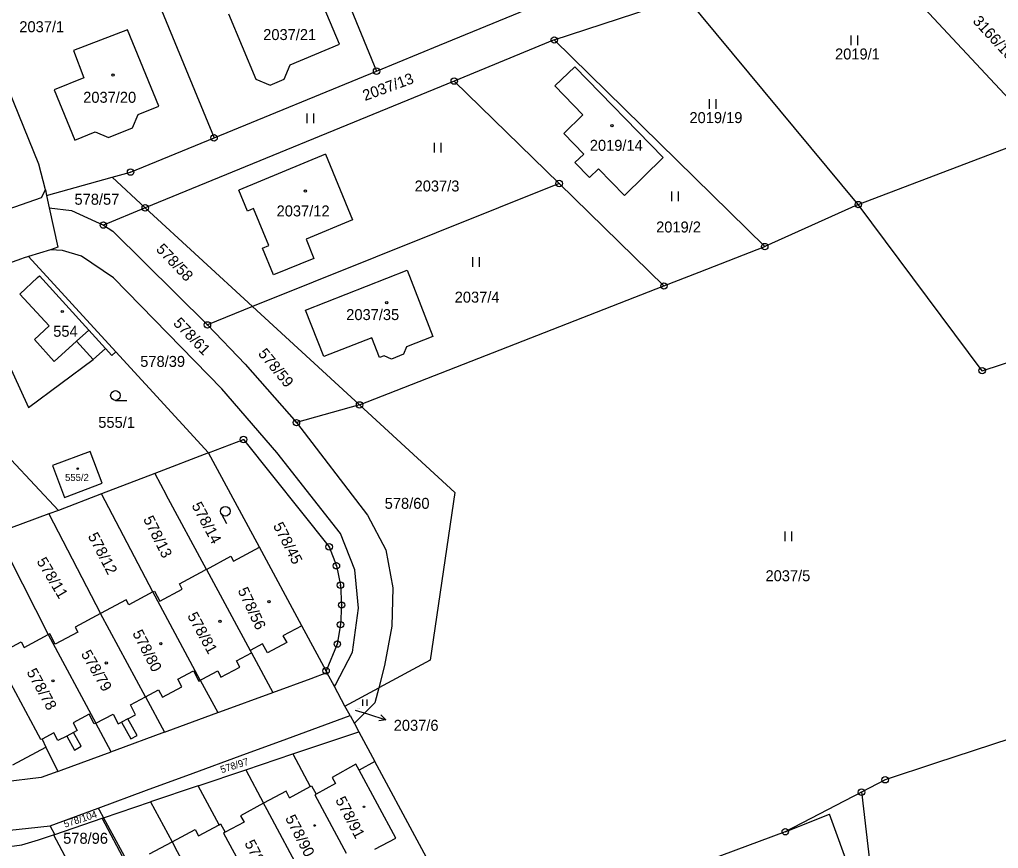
# Model space of a CAD drawing. Extents: x -736345 to -729997, y -1130177 to -1122501.
# Drawn here: x -732915.2 to -732763.4, y -1127440.7 to -1127312.1 of the extents above; entities that cross this region are included whole.
import ezdxf

# ---------------------------------------------------------------- set-up
doc = ezdxf.new("R2010")
doc.units = 0
for name, color, linetype in [('Vrstva 1', 7, 'Continuous'), ('Vrstva 16', 7, 'Continuous'), ('Vrstva 18', 7, 'Continuous'), ('Vrstva 19', 7, 'Continuous'), ('Vrstva 25', 7, 'Continuous'), ('Vrstva 4', 7, 'Continuous')]:
    doc.layers.add(name, color=color, linetype=linetype)

msp = doc.modelspace()

# ---------------------------------------------------------------- linework, layer by layer
at = {"layer": 'Vrstva 1'}
for points in [[(-732871.63, -1127291.34), (-732859.83, -1127320.07)], [(-732897.23, -1127300.77), (-732885.05, -1127330.42)], [(-732865.58, -1127315.91), (-732869.5, -1127306.54)], [(-732785.09, -1127340.77), (-732811.96, -1127308.4)], [(-732756.54, -1127329.92), (-732776.31, -1127308.71)], [(-732912.21, -1127334.51), (-732922.29, -1127309.89)], [(-732850.06, -1127316.06), (-732834.54, -1127309.69)], [(-732832.26, -1127315.24), (-732814.67, -1127309.5)], [(-732882.82, -1127311.18), (-732878.59, -1127321.32)], [(-732898.45, -1127313.65), (-732906.86, -1127316.88)], [(-732893.6, -1127325.52), (-732898.45, -1127313.65)], [(-732832.26, -1127315.24), (-732847.78, -1127321.61)], [(-732799.61, -1127347.29), (-732832.26, -1127315.24)], [(-732906.86, -1127316.88), (-732905.23, -1127321.12)], [(-732873.25, -1127319.1), (-732865.58, -1127315.91)], [(-732859.83, -1127320.07), (-732850.06, -1127316.06)], [(-732874.17, -1127321.33), (-732873.25, -1127319.1)], [(-732829.06, -1127319.42), (-732832.2, -1127322.34)], [(-732815.36, -1127333.49), (-732829.06, -1127319.42)], [(-732905.23, -1127321.12), (-732909.83, -1127322.96)], [(-732885.05, -1127330.42), (-732859.83, -1127320.07)], [(-732878.59, -1127321.32), (-732876.36, -1127322.27)], [(-732876.36, -1127322.27), (-732874.17, -1127321.33)], [(-732909.83, -1127322.96), (-732906.66, -1127330.76)], [(-732847.78, -1127321.61), (-732895.72, -1127341.28)], [(-732831.51, -1127337.5), (-732847.78, -1127321.61)], [(-732832.2, -1127322.34), (-732827.81, -1127326.83)], [(-732896.8, -1127326.81), (-732893.6, -1127325.52)], [(-732897.69, -1127328.87), (-732896.8, -1127326.81)], [(-732827.81, -1127326.83), (-732830.79, -1127329.75)], [(-732901.4, -1127330.35), (-732897.69, -1127328.87)], [(-732906.66, -1127330.76), (-732903.49, -1127329.49)], [(-732903.49, -1127329.49), (-732901.4, -1127330.35)], [(-732898, -1127335.73), (-732885.05, -1127330.42)], [(-732830.79, -1127329.75), (-732827.7, -1127332.95)], [(-732785.09, -1127340.77), (-732756.54, -1127329.92)], [(-732867.74, -1127332.97), (-732881.22, -1127338.52)], [(-732867.74, -1127332.97), (-732863.55, -1127343.14)], [(-732827.7, -1127332.95), (-732829.09, -1127334.25)], [(-732821.36, -1127339.35), (-732815.36, -1127333.49)], [(-732911.22, -1127338.5), (-732912.21, -1127334.51)], [(-732829.09, -1127334.25), (-732826.8, -1127336.59)], [(-732911.03, -1127339.37), (-732900.88, -1127336.53)], [(-732900.88, -1127336.53), (-732898, -1127335.73)], [(-732900.88, -1127336.53), (-732895.72, -1127341.28)], [(-732826.8, -1127336.59), (-732825.42, -1127335.21)], [(-732825.42, -1127335.21), (-732821.36, -1127339.35)], [(-732831.51, -1127337.5), (-732879.1, -1127356.57)], [(-732815.24, -1127353.4), (-732831.51, -1127337.5)], [(-732939.08, -1127349.18), (-732911.82, -1127339.65)], [(-732911.82, -1127339.65), (-732911.22, -1127338.5)], [(-732911.22, -1127338.5), (-732911.03, -1127339.37)], [(-732911.03, -1127339.37), (-732910.61, -1127341.26)], [(-732879.88, -1127341.79), (-732881.22, -1127338.52)], [(-732910.61, -1127341.26), (-732907.17, -1127341.69)], [(-732910.61, -1127341.26), (-732909.26, -1127347.36)], [(-732785.09, -1127340.77), (-732799.61, -1127347.29)], [(-732765.88, -1127366.54), (-732785.09, -1127340.77)], [(-732907.17, -1127341.69), (-732902.22, -1127343.95)], [(-732895.72, -1127341.28), (-732902.22, -1127343.95)], [(-732895.72, -1127341.28), (-732879.1, -1127356.57)], [(-732878.93, -1127341.4), (-732879.88, -1127341.79)], [(-732876.57, -1127347.12), (-732878.93, -1127341.4)], [(-732902.22, -1127343.95), (-732900.74, -1127344.92)], [(-732863.55, -1127343.14), (-732870.78, -1127346.16)], [(-732900.74, -1127344.92), (-732886.08, -1127359.44)], [(-732877.52, -1127347.51), (-732876.57, -1127347.12)], [(-732870.78, -1127346.16), (-732869.56, -1127349.14)], [(-732809.76, -1127351.26), (-732799.61, -1127347.29)], [(-732913.86, -1127348.82), (-732914.65, -1127349.1)], [(-732910.43, -1127347.79), (-732913.86, -1127348.82)], [(-732900.29, -1127363.61), (-732913.86, -1127348.82)], [(-732909.26, -1127347.36), (-732910.43, -1127347.79)], [(-732908.54, -1127347.88), (-732910.43, -1127347.79)], [(-732905.63, -1127348.8), (-732908.54, -1127347.88)], [(-732900.66, -1127352.13), (-732905.63, -1127348.8)], [(-732875.8, -1127351.69), (-732877.52, -1127347.51)], [(-732914.93, -1127349.2), (-732923.1, -1127352.09)], [(-732914.65, -1127349.1), (-732914.93, -1127349.2)], [(-732869.56, -1127349.14), (-732875.8, -1127351.69)], [(-732870.84, -1127357.14), (-732855.1, -1127350.97), (-732851.08, -1127361.22), (-732855.18, -1127362.85), (-732855.65, -1127364), (-732857.52, -1127364.74), (-732858.67, -1127364.23), (-732859.37, -1127364.49), (-732860.58, -1127361.42), (-732868.02, -1127364.34), (-732870.84, -1127357.14)], [(-732815.24, -1127353.4), (-732809.76, -1127351.26)], [(-732923.1, -1127352.09), (-732913.85, -1127372.23)], [(-732883.85, -1127369.37), (-732900.66, -1127352.13)], [(-732862.47, -1127371.85), (-732815.24, -1127353.4)], [(-732879.1, -1127356.57), (-732886.08, -1127359.44)], [(-732879.1, -1127356.57), (-732862.47, -1127371.85)], [(-732765.88, -1127366.54), (-732737.77, -1127357.37)], [(-732886.08, -1127359.44), (-732880.22, -1127365.51)], [(-732903.79, -1127364.82), (-732901.9, -1127363.12)], [(-732901.9, -1127363.12), (-732900.93, -1127364.19)], [(-732900.93, -1127364.19), (-732900.29, -1127363.61)], [(-732900.29, -1127363.61), (-732885.9, -1127379.3)], [(-732913.85, -1127372.23), (-732903.79, -1127364.82)], [(-732880.22, -1127365.51), (-732872.27, -1127374.6)], [(-732875.33, -1127379.22), (-732883.85, -1127369.37)], [(-732923.9, -1127372.5), (-732909.17, -1127388.22)], [(-732862.47, -1127371.85), (-732872.27, -1127374.6)], [(-732862.47, -1127371.85), (-732847.71, -1127385.43)], [(-732872.27, -1127374.6), (-732861.24, -1127388.95)], [(-732885.9, -1127379.3), (-732880.48, -1127377.22)], [(-732880.48, -1127377.22), (-732867.18, -1127393.87)], [(-732904.29, -1127379.06), (-732910.12, -1127381.23)], [(-732902.43, -1127383.99), (-732904.29, -1127379.06)], [(-732865.43, -1127391.81), (-732875.33, -1127379.22)], [(-732885.9, -1127379.3), (-732894.24, -1127382.5)], [(-732885.19, -1127380.62), (-732885.9, -1127379.3)], [(-732878.01, -1127393.93), (-732885.19, -1127380.62)], [(-732910.12, -1127381.23), (-732908.27, -1127386.21)], [(-732894.24, -1127382.5), (-732902.5, -1127385.66)], [(-732894.24, -1127382.5), (-732892.47, -1127385.79)], [(-732908.27, -1127386.21), (-732902.43, -1127383.99)], [(-732902.5, -1127385.66), (-732909.17, -1127388.22)], [(-732894.53, -1127400.87), (-732902.5, -1127385.66)], [(-732886.23, -1127397.36), (-732892.47, -1127385.79)], [(-732847.71, -1127385.43), (-732851.53, -1127411.44)], [(-732909.17, -1127388.22), (-732910.67, -1127388.77)], [(-732910.67, -1127388.77), (-732918.8, -1127391.73)], [(-732910.67, -1127388.77), (-732902.65, -1127404.19)], [(-732861.24, -1127388.95), (-732858.41, -1127394.35)], [(-732918.8, -1127391.73), (-732910.76, -1127407.47)], [(-732863.23, -1127397.41), (-732865.43, -1127391.81)], [(-732882.03, -1127396.1), (-732878.01, -1127393.93)], [(-732871.45, -1127406.11), (-732878.01, -1127393.93)], [(-732867.18, -1127393.87), (-732866.07, -1127396.8)], [(-732858.41, -1127394.35), (-732857.3, -1127400.23)], [(-732886.23, -1127397.36), (-732882.46, -1127395.29)], [(-732882.46, -1127395.29), (-732882.03, -1127396.1)], [(-732886.23, -1127397.36), (-732886.48, -1127397.5)], [(-732886.23, -1127397.36), (-732879.42, -1127409.96)], [(-732866.07, -1127396.8), (-732865.44, -1127399.82)], [(-732862.65, -1127403.38), (-732863.23, -1127397.41)], [(-732890.41, -1127399.63), (-732886.48, -1127397.5)], [(-732893.47, -1127402.32), (-732889.98, -1127400.43)], [(-732889.98, -1127400.43), (-732890.41, -1127399.63)], [(-732865.44, -1127399.82), (-732865.25, -1127402.89)], [(-732857.3, -1127400.23), (-732857.48, -1127406.16)], [(-732894.53, -1127400.87), (-732898.28, -1127402.87)], [(-732894.53, -1127400.87), (-732894.3, -1127400.75)], [(-732887.18, -1127414.56), (-732894.53, -1127400.87)], [(-732894.3, -1127400.75), (-732893.47, -1127402.32)], [(-732898.7, -1127402.09), (-732902.65, -1127404.19)], [(-732898.28, -1127402.87), (-732898.7, -1127402.09)], [(-732865.25, -1127402.89), (-732865.43, -1127405.94)], [(-732863.55, -1127410.23), (-732862.65, -1127403.38)], [(-732902.65, -1127404.19), (-732906.61, -1127406.31)], [(-732895.66, -1127417.15), (-732902.65, -1127404.19)], [(-732906.61, -1127406.31), (-732906.2, -1127407.09)], [(-732867.67, -1127413.11), (-732871.45, -1127406.11)], [(-732865.43, -1127405.94), (-732865.92, -1127408.95)], [(-732857.48, -1127406.16), (-732858.62, -1127412.26)], [(-732914.51, -1127409.46), (-732910.76, -1127407.47)], [(-732910.54, -1127407.36), (-732910.76, -1127407.47)], [(-732910.76, -1127407.47), (-732903.4, -1127421.22)], [(-732909.69, -1127408.95), (-732910.54, -1127407.36)], [(-732906.2, -1127407.09), (-732909.69, -1127408.95)], [(-732918.93, -1127410.73), (-732914.95, -1127408.62)], [(-732914.95, -1127408.62), (-732914.51, -1127409.46)], [(-732865.92, -1127408.95), (-732867.67, -1127413.11)], [(-732911.93, -1127423.77), (-732918.93, -1127410.73)], [(-732879.42, -1127409.96), (-732879.25, -1127410.3)], [(-732879.25, -1127410.3), (-732875.93, -1127416.45)], [(-732866.21, -1127415.27), (-732863.55, -1127410.23)], [(-732851.53, -1127411.44), (-732859.5, -1127415.74)], [(-732858.62, -1127412.26), (-732859.5, -1127415.74)], [(-732869.98, -1127414.27), (-732867.53, -1127413.37)], [(-732867.67, -1127413.11), (-732867.53, -1127413.37)], [(-732866.36, -1127415.55), (-732867.53, -1127413.37)], [(-732887.18, -1127414.56), (-732884.48, -1127419.59)], [(-732875.93, -1127416.45), (-732869.98, -1127414.27)], [(-732866.36, -1127415.55), (-732866.21, -1127415.27)], [(-732864.74, -1127418.56), (-732866.36, -1127415.55)], [(-732895.66, -1127417.15), (-732892.71, -1127422.62)], [(-732884.14, -1127419.47), (-732875.93, -1127416.45)], [(-732864.74, -1127418.56), (-732859.5, -1127415.74)], [(-732859.5, -1127415.74), (-732860.09, -1127418.07)], [(-732863.94, -1127420.04), (-732864.74, -1127418.56)], [(-732860.09, -1127418.07), (-732863.13, -1127421.14)], [(-732892.34, -1127422.48), (-732884.48, -1127419.59)], [(-732884.48, -1127419.59), (-732884.14, -1127419.47)], [(-732873.77, -1127423.65), (-732863.94, -1127420.04)], [(-732863.94, -1127420.04), (-732863.27, -1127421.28)], [(-732901.03, -1127425.66), (-732903.4, -1127421.22)], [(-732863.27, -1127421.28), (-732863.13, -1127421.14)], [(-732863.27, -1127421.28), (-732862.57, -1127422.58)], [(-732892.71, -1127422.62), (-732900.55, -1127425.49)], [(-732892.71, -1127422.62), (-732892.34, -1127422.48)], [(-732872.83, -1127426), (-732862.57, -1127422.58)], [(-732862.57, -1127422.58), (-732860.08, -1127427.19)], [(-732911.72, -1127423.72), (-732911.93, -1127423.77)], [(-732911.72, -1127423.72), (-732911.13, -1127424.93)], [(-732881.02, -1127426.31), (-732873.77, -1127423.65)], [(-732761.42, -1127423.6), (-732773.12, -1127427.44)], [(-732911.13, -1127424.93), (-732909.29, -1127428.7)], [(-732908.75, -1127428.5), (-732901.03, -1127425.66)], [(-732900.55, -1127425.49), (-732901.03, -1127425.66)], [(-732888.28, -1127428.97), (-732881.02, -1127426.31)], [(-732880.13, -1127428.44), (-732872.83, -1127426)], [(-732872.83, -1127426), (-732870.12, -1127431.05)], [(-732860.08, -1127427.19), (-732862.51, -1127428.53)], [(-732846.94, -1127451.57), (-732860.08, -1127427.19)], [(-732773.12, -1127427.44), (-732780.92, -1127430)], [(-732909.29, -1127428.7), (-732911.86, -1127429.65)], [(-732909.29, -1127428.7), (-732908.75, -1127428.5)], [(-732895.53, -1127431.64), (-732888.28, -1127428.97)], [(-732887.51, -1127430.93), (-732880.13, -1127428.44)], [(-732880.13, -1127428.44), (-732877.35, -1127433.65)], [(-732856.82, -1127439.08), (-732862.51, -1127428.53)], [(-732911.86, -1127429.65), (-732917.83, -1127430.37)], [(-732780.92, -1127430), (-732784.6, -1127431.92)], [(-732903.01, -1127434.39), (-732895.53, -1127431.64)], [(-732887.51, -1127430.93), (-732894.9, -1127433.43)], [(-732884.27, -1127436.97), (-732887.51, -1127430.93)], [(-732870.12, -1127431.05), (-732869.91, -1127430.94)], [(-732869.91, -1127430.94), (-732869.22, -1127432.23)], [(-732869.22, -1127432.23), (-732869.43, -1127432.35)], [(-732869.43, -1127432.35), (-732864.57, -1127441.39)], [(-732784.6, -1127431.92), (-732796.42, -1127438.06)], [(-732784.6, -1127431.92), (-732784.56, -1127432.3)], [(-732784.56, -1127432.3), (-732778.3, -1127486.15)], [(-732902.19, -1127435.9), (-732894.9, -1127433.43)], [(-732894.9, -1127433.43), (-732891.55, -1127439.62)], [(-732876.81, -1127434.65), (-732877.35, -1127433.65)], [(-732910.49, -1127437.13), (-732903.01, -1127434.39)], [(-732903.01, -1127434.39), (-732902.86, -1127434.67)], [(-732902.86, -1127434.67), (-732902.19, -1127435.9)], [(-732871.29, -1127445), (-732876.81, -1127434.65)], [(-732796.42, -1127438.06), (-732789.55, -1127435.35)], [(-732782.65, -1127454.43), (-732789.55, -1127435.35)], [(-732909.76, -1127438.48), (-732902.41, -1127435.98)], [(-732902.41, -1127435.98), (-732902.19, -1127435.9)], [(-732898.72, -1127442.87), (-732902.41, -1127435.98)], [(-732902.19, -1127435.9), (-732897.72, -1127444.2)], [(-732884.27, -1127436.97), (-732884.03, -1127436.85)], [(-732884.03, -1127436.85), (-732883.33, -1127438.15)], [(-732918.7, -1127438.04), (-732910.49, -1127437.13)], [(-732910.43, -1127437.24), (-732910.49, -1127437.13)], [(-732909.76, -1127438.48), (-732910.43, -1127437.24)], [(-732883.33, -1127438.15), (-732883.59, -1127438.29)], [(-732883.59, -1127438.29), (-732878.64, -1127447.46)], [(-732796.42, -1127438.06), (-732827.88, -1127449.76)], [(-732914.89, -1127440.1), (-732912.26, -1127439.34)], [(-732912.26, -1127439.34), (-732909.94, -1127438.54)], [(-732909.94, -1127438.54), (-732909.76, -1127438.48)], [(-732909.94, -1127438.54), (-732906.11, -1127445.71)], [(-732891.55, -1127439.62), (-732891.02, -1127440.6)], [(-732860.12, -1127440.78), (-732856.82, -1127439.08)], [(-732917.57, -1127440.47), (-732914.89, -1127440.1)], [(-732885.36, -1127451.06), (-732891.02, -1127440.6)]]:
    msp.add_lwpolyline(points, dxfattribs=at)
at = {"layer": 'Vrstva 16'}
msp.add_lwpolyline([(-732863.14, -1127419.18), (-732861.23, -1127419.79)], dxfattribs=at)
at = {"layer": 'Vrstva 25'}
for points in [[(-732786.207, -1127316.025), (-732786.207, -1127314.525)], [(-732785.173, -1127316.025), (-732785.173, -1127314.525)], [(-732808.187, -1127325.895), (-732808.187, -1127324.395)], [(-732807.153, -1127325.895), (-732807.153, -1127324.395)], [(-732870.607, -1127328.135), (-732870.607, -1127326.635)], [(-732869.573, -1127328.135), (-732869.573, -1127326.635)], [(-732850.847, -1127332.715), (-732850.847, -1127331.215)], [(-732849.813, -1127332.715), (-732849.813, -1127331.215)], [(-732814.007, -1127340.235), (-732814.007, -1127338.735)], [(-732812.973, -1127340.235), (-732812.973, -1127338.735)], [(-732844.887, -1127350.435), (-732844.887, -1127348.935)], [(-732843.853, -1127350.435), (-732843.853, -1127348.935)], [(-732900.34, -1127371.14), (-732898.59, -1127371.14)], [(-732883.96, -1127388.71), (-732883.101, -1127390.234)], [(-732796.427, -1127392.985), (-732796.427, -1127391.485)], [(-732795.393, -1127392.985), (-732795.393, -1127391.485)], [(-732861.976, -1127418.542), (-732861.976, -1127417.537)], [(-732861.283, -1127418.542), (-732861.283, -1127417.537)], [(-732861.23, -1127419.79), (-732858.374, -1127420.707)], [(-732859.173, -1127419.925), (-732858.374, -1127420.707), (-732859.479, -1127420.877)]]:
    msp.add_lwpolyline(points, dxfattribs=at)
for centre, radius in [((-732832.26, -1127315.24), 0.5), ((-732832.26, -1127315.24), 0.032), ((-732859.83, -1127320.07), 0.5), ((-732900.72, -1127320.68), 0.175), ((-732859.83, -1127320.07), 0.032), ((-732847.78, -1127321.61), 0.5), ((-732847.78, -1127321.61), 0.032), ((-732823.32, -1127328.53), 0.175), ((-732885.05, -1127330.42), 0.5), ((-732885.05, -1127330.42), 0.032), ((-732898, -1127335.73), 0.5), ((-732898, -1127335.73), 0.032), ((-732831.51, -1127337.5), 0.5), ((-732831.51, -1127337.5), 0.032), ((-732870.87, -1127338.68), 0.175), ((-732895.72, -1127341.28), 0.5), ((-732895.72, -1127341.28), 0.032), ((-732785.09, -1127340.77), 0.5), ((-732785.09, -1127340.77), 0.032), ((-732902.22, -1127343.95), 0.499), ((-732902.22, -1127343.95), 0.0318), ((-732799.61, -1127347.29), 0.5), ((-732799.61, -1127347.29), 0.032), ((-732815.24, -1127353.4), 0.5), ((-732815.24, -1127353.4), 0.032), ((-732858.25, -1127356), 0.175), ((-732908.59, -1127357.36), 0.175), ((-732886.08, -1127359.44), 0.5), ((-732886.08, -1127359.44), 0.032), ((-732765.88, -1127366.54), 0.5), ((-732765.88, -1127366.54), 0.032), ((-732900.34, -1127370.39), 0.75), ((-732862.47, -1127371.85), 0.5), ((-732862.47, -1127371.85), 0.032), ((-732872.27, -1127374.6), 0.5), ((-732872.27, -1127374.6), 0.032), ((-732880.48, -1127377.22), 0.5), ((-732880.48, -1127377.22), 0.032), ((-732906.189, -1127381.73), 0.118), ((-732883.307, -1127388.342), 0.75), ((-732867.18, -1127393.87), 0.5), ((-732867.18, -1127393.87), 0.032), ((-732866.07, -1127396.8), 0.5), ((-732866.07, -1127396.8), 0.032), ((-732865.44, -1127399.82), 0.5), ((-732865.44, -1127399.82), 0.032), ((-732876.54, -1127402.37), 0.175), ((-732865.25, -1127402.89), 0.5), ((-732865.25, -1127402.89), 0.032), ((-732884.13, -1127405.41), 0.175), ((-732865.43, -1127405.94), 0.5), ((-732865.43, -1127405.94), 0.032), ((-732893.31, -1127408.87), 0.174), ((-732865.92, -1127408.95), 0.5), ((-732865.92, -1127408.95), 0.032), ((-732901.77, -1127411.87), 0.175), ((-732867.67, -1127413.11), 0.5), ((-732867.67, -1127413.11), 0.032), ((-732910.04, -1127414.65), 0.175), ((-732780.92, -1127430), 0.5), ((-732780.92, -1127430), 0.032), ((-732784.6, -1127431.92), 0.5), ((-732784.6, -1127431.92), 0.032), ((-732861.78, -1127434.2), 0.118), ((-732869.419, -1127437.09), 0.118), ((-732796.42, -1127438.06), 0.5), ((-732796.42, -1127438.06), 0.032)]:
    msp.add_circle(centre, radius, dxfattribs=at)
at = {"layer": 'Vrstva 4'}
for points in [[(-732912.43, -1127352.09), (-732912.14, -1127351.82)], [(-732904.5, -1127360.23), (-732912.14, -1127351.82)], [(-732912.43, -1127352.09), (-732915.19, -1127354.67)], [(-732915.19, -1127354.67), (-732910.63, -1127359.58)], [(-732910.63, -1127359.58), (-732912.93, -1127361.71)], [(-732906.4, -1127361.96), (-732904.5, -1127360.23)], [(-732901.9, -1127363.12), (-732904.5, -1127360.23)], [(-732912.93, -1127361.71), (-732909.83, -1127365.12)], [(-732909.83, -1127365.12), (-732906.4, -1127361.96)], [(-732906.4, -1127361.96), (-732903.79, -1127364.82)], [(-732871.45, -1127406.11), (-732874.35, -1127407.67)], [(-732874.35, -1127407.67), (-732873.77, -1127408.73)], [(-732877.51, -1127408.93), (-732879.42, -1127409.96)], [(-732876.73, -1127410.33), (-732877.51, -1127408.93)], [(-732873.77, -1127408.73), (-732876.73, -1127410.33)], [(-732881.55, -1127411.54), (-732879.25, -1127410.3)], [(-732883.99, -1127414.06), (-732881.06, -1127412.52)], [(-732881.06, -1127412.52), (-732881.55, -1127411.54)], [(-732890.68, -1127414.42), (-732888.24, -1127413.09)], [(-732888.24, -1127413.09), (-732887.39, -1127414.68)], [(-732886.87, -1127414.4), (-732884.47, -1127413.11)], [(-732884.47, -1127413.11), (-732883.99, -1127414.06)], [(-732893.07, -1127417.2), (-732890.06, -1127415.59)], [(-732890.06, -1127415.59), (-732890.68, -1127414.42)], [(-732887.39, -1127414.68), (-732887.18, -1127414.56)], [(-732887.18, -1127414.56), (-732886.87, -1127414.4)], [(-732898.03, -1127418.4), (-732895.66, -1127417.15)], [(-732895.66, -1127417.15), (-732893.68, -1127416.05)], [(-732893.68, -1127416.05), (-732893.07, -1127417.2)], [(-732897.21, -1127419.91), (-732898.03, -1127418.4)], [(-732904.44, -1127419.81), (-732906.93, -1127421.15)], [(-732903.63, -1127421.34), (-732904.44, -1127419.81)], [(-732903.4, -1127421.22), (-732900.71, -1127419.81)], [(-732900.71, -1127419.81), (-732899.9, -1127421.33)], [(-732898.4, -1127420.57), (-732897.21, -1127419.91)], [(-732906.93, -1127421.15), (-732906.26, -1127422.34)], [(-732903.4, -1127421.22), (-732903.63, -1127421.34)], [(-732899.9, -1127421.33), (-732899.39, -1127421.09)], [(-732898.4, -1127420.57), (-732899.39, -1127421.09)], [(-732899.39, -1127421.09), (-732897.95, -1127423.63)], [(-732896.96, -1127423.13), (-732898.4, -1127420.57)], [(-732909.9, -1127422.74), (-732911.72, -1127423.72)], [(-732909.3, -1127423.93), (-732909.9, -1127422.74)], [(-732907.91, -1127423.22), (-732909.3, -1127423.93)], [(-732906.86, -1127422.65), (-732907.91, -1127423.22)], [(-732907.91, -1127423.22), (-732906.72, -1127425.39)], [(-732906.26, -1127422.34), (-732906.86, -1127422.65)], [(-732905.67, -1127424.81), (-732906.86, -1127422.65)], [(-732897.95, -1127423.63), (-732896.96, -1127423.13)], [(-732916.25, -1127427.67), (-732911.13, -1127424.93)], [(-732906.72, -1127425.39), (-732905.67, -1127424.81)], [(-732863.03, -1127427.59), (-732866.74, -1127429.64)], [(-732862.51, -1127428.53), (-732863.03, -1127427.59)], [(-732866.22, -1127430.58), (-732869.22, -1127432.23)], [(-732866.74, -1127429.64), (-732866.22, -1127430.58)], [(-732873.86, -1127431.77), (-732877.35, -1127433.65)], [(-732873.33, -1127432.78), (-732873.86, -1127431.77)], [(-732873.33, -1127432.78), (-732870.12, -1127431.05)], [(-732877.35, -1127433.65), (-732880.92, -1127435.58)], [(-732880.38, -1127436.57), (-732883.33, -1127438.15)], [(-732880.92, -1127435.58), (-732880.38, -1127436.57)], [(-732891.55, -1127439.62), (-732887.99, -1127437.71)], [(-732887.99, -1127437.71), (-732887.47, -1127438.69)], [(-732887.47, -1127438.69), (-732884.27, -1127436.97)], [(-732895.05, -1127441.49), (-732891.55, -1127439.62)]]:
    msp.add_lwpolyline(points, dxfattribs=at)

# ---------------------------------------------------------------- texts
at = {"layer": 'Vrstva 16'}
for s, p in [('2037/6', (-732857.17, -1127422.4)), ('578/96', (-732908.457, -1127439.93))]:
    msp.add_text(s, height=1.7, dxfattribs=at).set_placement(p)
at = {"layer": 'Vrstva 18'}
for s, height, p in [('2037/1', 1.7, (-732915.26, -1127314.03)), ('2019/1', 1.7, (-732788.7, -1127318.26)), ('2019/19', 1.7, (-732811.29, -1127328.13)), ('2037/3', 1.7, (-732853.93, -1127338.74)), ('578/57', 1.7, (-732906.7, -1127340.8)), ('2019/2', 1.7, (-732816.46, -1127345.1)), ('2037/4', 1.7, (-732847.71, -1127355.98)), ('578/39', 1.7, (-732896.5, -1127365.95)), ('555/1', 1.7, (-732903.01, -1127375.41)), ('578/60', 1.7, (-732858.57, -1127387.97)), ('2037/5', 1.7, (-732799.49, -1127399.2)), ('2037/6', 0.1, (-732862.94, -1127418.98))]:
    msp.add_text(s, height=height, dxfattribs=at).set_placement(p)
for s, height, rotation, p in [('3166/16', 1.7, 312.60249, (-732767.438, -1127312.401)), ('2037/13', 1.7, 20.20016, (-732861.622, -1127324.714)), ('578/58', 1.7, 313.70249, (-732894.158, -1127347.806)), ('578/61', 1.7, 313.80249, (-732891.488, -1127359.275)), ('578/59', 1.7, 309.50246, (-732878.299, -1127363.937)), ('578/14', 1.7, 298.00237, (-732888.58, -1127387.452)), ('578/13', 1.7, 296.50236, (-732896.082, -1127389.559)), ('578/45', 1.7, 297.30236, (-732875.941, -1127390.575)), ('578/12', 1.7, 297.30236, (-732904.671, -1127392.175)), ('578/11', 1.7, 300.90239, (-732912.636, -1127396.118)), ('578/97', 1.1, 17.60014, (-732883.87, -1127428.999)), ('578/104', 1.1, 18.00014, (-732908.162, -1127437.448))]:
    msp.add_text(s, height=height, rotation=rotation, dxfattribs=at).set_placement(p)
at = {"layer": 'Vrstva 19'}
for s, height, p in [('2037/21', 1.7, (-732877.42, -1127315.25)), ('2037/20', 1.7, (-732905.35, -1127324.98)), ('2019/14', 1.7, (-732826.75, -1127332.43)), ('2037/12', 1.7, (-732875.34, -1127342.61)), ('2037/35', 1.7, (-732864.538, -1127358.69)), ('554', 1.7, (-732910, -1127361.28)), ('555/2', 1.1, (-732908.16, -1127383.65))]:
    msp.add_text(s, height=height, dxfattribs=at).set_placement(p)
for s, rotation, p in [('578/56', 295.10235, (-732881.415, -1127400.616)), ('578/81', 298.70238, (-732889.249, -1127404.559)), ('578/80', 297.30236, (-732897.761, -1127407.265)), ('578/79', 300.10239, (-732905.747, -1127410.472)), ('578/78', 298.70238, (-732914.179, -1127413.289)), ('578/91', 297.50237, (-732866.281, -1127433.135)), ('578/90', 297.20236, (-732874.051, -1127435.956)), ('578/89', 297.40237, (-732880.371, -1127439.845))]:
    msp.add_text(s, height=1.7, rotation=rotation, dxfattribs=at).set_placement(p)

doc.saveas('drawing.dxf')
